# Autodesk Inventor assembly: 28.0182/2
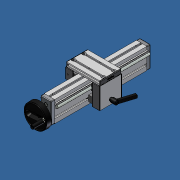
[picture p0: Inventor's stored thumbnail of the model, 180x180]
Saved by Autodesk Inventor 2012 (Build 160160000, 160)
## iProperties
Created: 2007-06
Part Number: 28.0182/2
Document SubType Name: Assembly
Designer: Andy Moles
Description: ADJUSTING UNIT VEW 45X90H WITH SIDE CLAMP
Author: Andy Moles
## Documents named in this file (24)
- C:\Andys Backup Data\ANDY'S INVENTOR\INVENTOR LIBRARIES\PARTS LIBRARY\READY FOR USE MODULES LG\28.0182_2 ADJUSTING UNIT VEW 45X90H WITH SIDE CLAMP.iam
- C:\Andys Backup Data\ANDY'S INVENTOR\INVENTOR LIBRARIES\PARTS LIBRARY\READY FOR USE MODULES LG\SUBCOMPONENTS\50.1264 BALL BEARING 10X30X9 6200 2RS DIN 625.ipt
- C:\Andys Backup Data\ANDY'S INVENTOR\INVENTOR LIBRARIES\PARTS LIBRARY\READY FOR USE MODULES LG\SUBCOMPONENTS\28.0200 BEARING PLATE 45X90 HANDWHEEL SIDE.ipt
- C:\Andys Backup Data\ANDY'S INVENTOR\INVENTOR LIBRARIES\PARTS LIBRARY\READY FOR USE MODULES LG\SUBCOMPONENTS\28.0201 BEARING PLATE 45X90 IDLER SIDE.ipt
- C:\Andys Backup Data\ANDY'S INVENTOR\INVENTOR LIBRARIES\PARTS LIBRARY\FASTENING ELEMENTS\SCREWS CAP\21.1204 M8X25.ipt
- C:\Andys Backup Data\ANDY'S INVENTOR\INVENTOR LIBRARIES\PARTS LIBRARY\FASTENING ELEMENTS\NUTS\21.1351 M8 SQUARE NUT.ipt
- C:\Andys Backup Data\ANDY'S INVENTOR\INVENTOR LIBRARIES\PARTS LIBRARY\READY FOR USE MODULES LG\SUBCOMPONENTS\28.0204 HANDWHEEL 100mm.iam
- C:\Andys Backup Data\ANDY'S INVENTOR\INVENTOR LIBRARIES\PARTS LIBRARY\READY FOR USE MODULES LG\SUBCOMPONENTS\28.0214 RAIL 45X90H.iam
- C:\Andys Backup Data\ANDY'S INVENTOR\INVENTOR LIBRARIES\PARTS LIBRARY\FASTENING ELEMENTS\WASHERS\21.1326 DISC SPRING 20.ipt
- C:\Andys Backup Data\ANDY'S INVENTOR\INVENTOR LIBRARIES\PARTS LIBRARY\READY FOR USE MODULES LG\SUBCOMPONENTS\28.0221 ACME SCREW 16X4.ipt
- C:\Andys Backup Data\ANDY'S INVENTOR\INVENTOR LIBRARIES\PARTS LIBRARY\READY FOR USE MODULES LG\SUBCOMPONENTS\28.0223_1 LWG 32X45-45 90X19-NSC.ipt
- C:\Andys Backup Data\ANDY'S INVENTOR\INVENTOR LIBRARIES\PARTS LIBRARY\READY FOR USE MODULES LG\SUBCOMPONENTS\28.0126 SLIDE 45X32.ipt
- C:\Andys Backup Data\ANDY'S INVENTOR\INVENTOR LIBRARIES\PARTS LIBRARY\FASTENING ELEMENTS\SCREWS CAP\21.1200 M8X16.ipt
- C:\Andys Backup Data\ANDY'S INVENTOR\INVENTOR LIBRARIES\PARTS LIBRARY\FASTENING ELEMENTS\SCREWS CAP\21.1235 M5X16.ipt
- C:\Andys Backup Data\ANDY'S INVENTOR\INVENTOR LIBRARIES\PARTS LIBRARY\END CAPS\22.1003_1 END CAP 45x32 Z Gray.iam
- C:\Andys Backup Data\ANDY'S INVENTOR\INVENTOR LIBRARIES\PARTS LIBRARY\READY FOR USE MODULES LG\SUBCOMPONENTS\28.9126 SIDE CLAMP 90X32.ipt
- C:\Andys Backup Data\ANDY'S INVENTOR\INVENTOR LIBRARIES\PARTS LIBRARY\COMPONENTS LG\22.1094 SLIDE RAIL LG.iam
- C:\Andys Backup Data\ANDY'S INVENTOR\INVENTOR LIBRARIES\PARTS LIBRARY\READY FOR USE MODULES LG\SUBCOMPONENTS\28.0256 Nut slide connector 38.5.ipt
- C:\Andys Backup Data\ANDY'S INVENTOR\INVENTOR LIBRARIES\PARTS LIBRARY\READY FOR USE MODULES LG\SUBCOMPONENTS\28.9127 SIDE LOCK SLIDE BAR 23.ipt
- C:\Andys Backup Data\ANDY'S INVENTOR\INVENTOR LIBRARIES\PARTS LIBRARY\COMPONENTS LG\21.1014_1 SLIDE LOCK WITH M6X65 STUD.ipt
- C:\Andys Backup Data\ANDY'S INVENTOR\INVENTOR LIBRARIES\PARTS LIBRARY\FASTENING ELEMENTS\NUTS\21.1330 M6 SQUARE NUT.ipt
- C:\Andys Backup Data\ANDY'S INVENTOR\INVENTOR LIBRARIES\PARTS LIBRARY\END CAPS\22.1014_1 END CAP 90X19 GRAY.ipt
- C:\Andys Backup Data\ANDY'S INVENTOR\INVENTOR LIBRARIES\PARTS LIBRARY\END CAPS\22.1061_1 END CAP 90X32 GRAY.ipt
- C:\Andys Backup Data\ANDY'S INVENTOR\INVENTOR LIBRARIES\PARTS LIBRARY\READY FOR USE MODULES LG\SUBCOMPONENTS\28.0257 BRONZE NUT 16X4 NOTCHED.ipt
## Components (39 placed, 23 different names)
1. 28.0214 RAIL 45X90H:1 [sub-assembly] — Mate:10, Flush:8, Flush:9, Flush:10, Flush:11, Flush:12, Mate:12, Flush:13, Flush:14, Angle:12, Angle:13, Mate:40
2. 50.1264 10X30X9 6200 2RS DIN 625 BALL BEARING:1 — Insert:11
3. 50.1264 10X30X9 6200 2RS DIN 625 BALL BEARING:2 — Insert:10, Insert:14
4. 28.0200 BEARING PLATE 45X90 HANDWHEEL SIDE:1 — Insert:4, Insert:5, Insert:9, Insert:11, Angle:2, Mate:12, Flush:13, Flush:14, Angle:14
5. 28.0201 BEARING PLATE 45X90 IDLER SIDE:1 — Insert:6, Insert:7, Insert:10, Angle:2, Mate:10, Flush:8, Flush:9
6. 21.1204  M8 x 25:1 — Insert:4
7. 21.1204  M8 x 25:2 — Insert:5
8. 21.1204  M8 x 25:3 — Insert:6
9. 21.1204  M8 x 25:4 — Insert:7
10. 28.0204 HANDWHEEL 100mm:1 [sub-assembly] — Insert:9
11. 21.1326 DISC SPRING 20:1 — Insert:12
12. 21.1326 DISC SPRING 20:2 — Insert:13, Insert:14
13. 28.0221 ACME SCREW 16X4:1 — Insert:12, Insert:13, Mate:39
14. 28.0223_1 LWG 32X45-45 90X19-NSC:1 — Mate:16, Flush:15, Flush:16, Insert:15, Insert:16, Insert:17, Insert:18, Insert:19, Insert:20, Mate:26, Flush:17, Flush:18, Flush:20, Angle:8, Insert:23, Angle:9, Mate:35, Flush:21, Mate:36, Flush:23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
15. 28.0126 SLIDE 45X32:1 — Mate:16, Flush:15, Flush:16, Mate:20, Mate:21, Angle:4, Angle:5, Mate:27, Insert:21, Insert:22, Angle:6, Angle:7, Mate:30, Mate:31
16. 21.1200 M8 x 16:1 — Insert:15, Mate:25
17. 21.1200 M8 x 16:2 — Insert:18, Mate:24
18. 21.1200 M8 x 16:3 — Insert:17, Mate:22
19. 21.1200 M8 x 16:4 — Insert:16, Mate:23
20. 21.1235  M5 x 16:1 — Insert:19
21. 21.1235  M5 x 16:2 — Insert:20
22. 21.1351 M8 SQUARE NUT:2 — Mate:24, Angle:4, Mate:27
23. 21.1351 M8 SQUARE NUT:3 — Mate:23, Mate:32, Angle:8
24. 21.1351 M8 SQUARE NUT:4 — Mate:20, Mate:25
25. 21.1351 M8 SQUARE NUT:5 — Mate:21, Mate:22, Angle:5
26. 22.1003\1 END CAP 45x32 Z Gray:1 [sub-assembly] — Insert:22, Angle:6
27. 22.1003\1 END CAP 45x32 Z Gray:2 [sub-assembly] — Insert:21, Angle:7
28. 28.9126 SIDE CLAMP 90X32:1 — Mate:26, Flush:17, Flush:18, Mate:28, Flush:19, Mate:29, Mate:32, Mate:33, Mate:34, Angle:10, Insert:24, Flush:22, Mate:37, Flush:25, Flush:26, Mate:38, Flush:27, Flush:28, Angle:12
29. 22.1094 SLIDE RAIL LG:1 [sub-assembly] — Mate:28, Flush:19, Mate:29
30. 22.1094 SLIDE RAIL LG:2 [sub-assembly] — Mate:30, Flush:20, Mate:31, Mate:40
31. 28.0256 Nut slide connector 38.5:1 — Insert:23, Angle:9, Mate:41
32. 28.9127 SIDE LOCK SLIDE BAR 23:1 — Mate:33, Mate:34, Angle:10, Angle:11, Mate:43
33. 21.1014_1 SLIDE LOCK WITH M6X65 STUD:1 — Insert:24, Mate:42
34. 21.1330 M6 SQUARE NUT:1 — Angle:11, Mate:42, Mate:43
35. 22.1014_1 END CAP 90X19 GRAY:1 — Mate:35, Flush:21, Flush:22
36. 22.1014_1 END CAP 90X19 GRAY:2 — Mate:36, Flush:23, Flush:24
37. 22.1061_1 END CAP 90X32 GRAY:1 — Mate:37, Flush:25, Flush:26
38. 22.1061_1 END CAP 90X32 GRAY:2 — Mate:38, Flush:27, Flush:28
39. 28.0257 BRONZE NUT 16X4 NOTCHED:1 — Mate:39, Angle:13, Angle:14, Mate:41
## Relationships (80: Mate 27, Flush 21, Insert 20, Angle 12)
- Insert:4: 28.0200 BEARING PLATE 45X90 HANDWHEEL SIDE:1 ↔ 21.1204  M8 x 25:1
- Insert:5: 28.0200 BEARING PLATE 45X90 HANDWHEEL SIDE:1 ↔ 21.1204  M8 x 25:2
- Insert:6: 28.0201 BEARING PLATE 45X90 IDLER SIDE:1 ↔ 21.1204  M8 x 25:3
- Insert:7: 28.0201 BEARING PLATE 45X90 IDLER SIDE:1 ↔ 21.1204  M8 x 25:4
- Insert:9: 28.0200 BEARING PLATE 45X90 HANDWHEEL SIDE:1 ↔ 28.0204 HANDWHEEL 100mm:1
- Insert:10: 50.1264 10X30X9 6200 2RS DIN 625 BALL BEARING:2 ↔ 28.0201 BEARING PLATE 45X90 IDLER SIDE:1
- Insert:11: 50.1264 10X30X9 6200 2RS DIN 625 BALL BEARING:1 ↔ 28.0200 BEARING PLATE 45X90 HANDWHEEL SIDE:1
- Angle:2: 28.0200 BEARING PLATE 45X90 HANDWHEEL SIDE:1 ↔ 28.0201 BEARING PLATE 45X90 IDLER SIDE:1
- Mate:10: 28.0214 RAIL 45X90H:1 ↔ 28.0201 BEARING PLATE 45X90 IDLER SIDE:1
- Flush:8: 28.0214 RAIL 45X90H:1 ↔ 28.0201 BEARING PLATE 45X90 IDLER SIDE:1
- Flush:9: 28.0214 RAIL 45X90H:1 ↔ 28.0201 BEARING PLATE 45X90 IDLER SIDE:1
- Flush:10: 28.0214 RAIL 45X90H:1
- Flush:11: 28.0214 RAIL 45X90H:1
- Flush:12: 28.0214 RAIL 45X90H:1
- Mate:12: 28.0214 RAIL 45X90H:1 ↔ 28.0200 BEARING PLATE 45X90 HANDWHEEL SIDE:1
- Flush:13: 28.0214 RAIL 45X90H:1 ↔ 28.0200 BEARING PLATE 45X90 HANDWHEEL SIDE:1
- Flush:14: 28.0214 RAIL 45X90H:1 ↔ 28.0200 BEARING PLATE 45X90 HANDWHEEL SIDE:1
- Insert:12: 21.1326 DISC SPRING 20:1 ↔ 28.0221 ACME SCREW 16X4:1
- Insert:13: 21.1326 DISC SPRING 20:2 ↔ 28.0221 ACME SCREW 16X4:1
- Insert:14: 50.1264 10X30X9 6200 2RS DIN 625 BALL BEARING:2 ↔ 21.1326 DISC SPRING 20:2
- Mate:16: 28.0223_1 LWG 32X45-45 90X19-NSC:1 ↔ 28.0126 SLIDE 45X32:1
- Flush:15: 28.0223_1 LWG 32X45-45 90X19-NSC:1 ↔ 28.0126 SLIDE 45X32:1
- Flush:16: 28.0223_1 LWG 32X45-45 90X19-NSC:1 ↔ 28.0126 SLIDE 45X32:1
- Insert:15: 28.0223_1 LWG 32X45-45 90X19-NSC:1 ↔ 21.1200 M8 x 16:1
- Insert:16: 28.0223_1 LWG 32X45-45 90X19-NSC:1 ↔ 21.1200 M8 x 16:4
- Insert:17: 28.0223_1 LWG 32X45-45 90X19-NSC:1 ↔ 21.1200 M8 x 16:3
- Insert:18: 28.0223_1 LWG 32X45-45 90X19-NSC:1 ↔ 21.1200 M8 x 16:2
- Insert:19: 28.0223_1 LWG 32X45-45 90X19-NSC:1 ↔ 21.1235  M5 x 16:1
- Insert:20: 28.0223_1 LWG 32X45-45 90X19-NSC:1 ↔ 21.1235  M5 x 16:2
- Mate:20: 28.0126 SLIDE 45X32:1 ↔ 21.1351 M8 SQUARE NUT:4
- Mate:21: 28.0126 SLIDE 45X32:1 ↔ 21.1351 M8 SQUARE NUT:5
- Mate:22: 21.1200 M8 x 16:3 ↔ 21.1351 M8 SQUARE NUT:5
- Mate:23: 21.1200 M8 x 16:4 ↔ 21.1351 M8 SQUARE NUT:3
- Mate:24: 21.1200 M8 x 16:2 ↔ 21.1351 M8 SQUARE NUT:2
- Mate:25: 21.1200 M8 x 16:1 ↔ 21.1351 M8 SQUARE NUT:4
- Angle:4: 28.0126 SLIDE 45X32:1 ↔ 21.1351 M8 SQUARE NUT:2
- Angle:5: 28.0126 SLIDE 45X32:1 ↔ 21.1351 M8 SQUARE NUT:5
- Mate:26: 28.0223_1 LWG 32X45-45 90X19-NSC:1 ↔ 28.9126 SIDE CLAMP 90X32:1
- Flush:17: 28.0223_1 LWG 32X45-45 90X19-NSC:1 ↔ 28.9126 SIDE CLAMP 90X32:1
- Flush:18: 28.0223_1 LWG 32X45-45 90X19-NSC:1 ↔ 28.9126 SIDE CLAMP 90X32:1
- Mate:27: 28.0126 SLIDE 45X32:1 ↔ 21.1351 M8 SQUARE NUT:2
- Insert:21: 28.0126 SLIDE 45X32:1 ↔ 22.1003\1 END CAP 45x32 Z Gray:2
- Insert:22: 28.0126 SLIDE 45X32:1 ↔ 22.1003\1 END CAP 45x32 Z Gray:1
- Angle:6: 28.0126 SLIDE 45X32:1 ↔ 22.1003\1 END CAP 45x32 Z Gray:1
- Angle:7: 28.0126 SLIDE 45X32:1 ↔ 22.1003\1 END CAP 45x32 Z Gray:2
- Mate:28: 28.9126 SIDE CLAMP 90X32:1 ↔ 22.1094 SLIDE RAIL LG:1
- Flush:19: 28.9126 SIDE CLAMP 90X32:1 ↔ 22.1094 SLIDE RAIL LG:1
- Mate:29: 28.9126 SIDE CLAMP 90X32:1 ↔ 22.1094 SLIDE RAIL LG:1
- Mate:30: 28.0126 SLIDE 45X32:1 ↔ 22.1094 SLIDE RAIL LG:2
- Flush:20: 28.0223_1 LWG 32X45-45 90X19-NSC:1 ↔ 22.1094 SLIDE RAIL LG:2
- Mate:31: 28.0126 SLIDE 45X32:1 ↔ 22.1094 SLIDE RAIL LG:2
- Mate:32: 21.1351 M8 SQUARE NUT:3 ↔ 28.9126 SIDE CLAMP 90X32:1
- Angle:8: 28.0223_1 LWG 32X45-45 90X19-NSC:1 ↔ 21.1351 M8 SQUARE NUT:3
- Insert:23: 28.0223_1 LWG 32X45-45 90X19-NSC:1 ↔ 28.0256 Nut slide connector 38.5:1
- Angle:9: 28.0223_1 LWG 32X45-45 90X19-NSC:1 ↔ 28.0256 Nut slide connector 38.5:1
- Mate:33: 28.9126 SIDE CLAMP 90X32:1 ↔ 28.9127 SIDE LOCK SLIDE BAR 23:1
- Mate:34: 28.9126 SIDE CLAMP 90X32:1 ↔ 28.9127 SIDE LOCK SLIDE BAR 23:1
- Angle:10: 28.9126 SIDE CLAMP 90X32:1 ↔ 28.9127 SIDE LOCK SLIDE BAR 23:1
- Insert:24: 28.9126 SIDE CLAMP 90X32:1 ↔ 21.1014_1 SLIDE LOCK WITH M6X65 STUD:1
- Angle:11: 28.9127 SIDE LOCK SLIDE BAR 23:1 ↔ 21.1330 M6 SQUARE NUT:1
- Mate:35: 28.0223_1 LWG 32X45-45 90X19-NSC:1 ↔ 22.1014_1 END CAP 90X19 GRAY:1
- Flush:21: 28.0223_1 LWG 32X45-45 90X19-NSC:1 ↔ 22.1014_1 END CAP 90X19 GRAY:1
- Flush:22: 28.9126 SIDE CLAMP 90X32:1 ↔ 22.1014_1 END CAP 90X19 GRAY:1
- Mate:36: 28.0223_1 LWG 32X45-45 90X19-NSC:1 ↔ 22.1014_1 END CAP 90X19 GRAY:2
- Flush:23: 28.0223_1 LWG 32X45-45 90X19-NSC:1 ↔ 22.1014_1 END CAP 90X19 GRAY:2
- Flush:24: 28.0223_1 LWG 32X45-45 90X19-NSC:1 ↔ 22.1014_1 END CAP 90X19 GRAY:2
- Mate:37: 28.9126 SIDE CLAMP 90X32:1 ↔ 22.1061_1 END CAP 90X32 GRAY:1
- Flush:25: 28.9126 SIDE CLAMP 90X32:1 ↔ 22.1061_1 END CAP 90X32 GRAY:1
- Flush:26: 28.9126 SIDE CLAMP 90X32:1 ↔ 22.1061_1 END CAP 90X32 GRAY:1
- Mate:38: 28.9126 SIDE CLAMP 90X32:1 ↔ 22.1061_1 END CAP 90X32 GRAY:2
- Flush:27: 28.9126 SIDE CLAMP 90X32:1 ↔ 22.1061_1 END CAP 90X32 GRAY:2
- Flush:28: 28.9126 SIDE CLAMP 90X32:1 ↔ 22.1061_1 END CAP 90X32 GRAY:2
- Angle:12: 28.0214 RAIL 45X90H:1 ↔ 28.9126 SIDE CLAMP 90X32:1
- Mate:39: 28.0221 ACME SCREW 16X4:1 ↔ 28.0257 BRONZE NUT 16X4 NOTCHED:1
- Angle:13: 28.0214 RAIL 45X90H:1 ↔ 28.0257 BRONZE NUT 16X4 NOTCHED:1
- Angle:14: 28.0200 BEARING PLATE 45X90 HANDWHEEL SIDE:1 ↔ 28.0257 BRONZE NUT 16X4 NOTCHED:1
- Mate:40: 28.0214 RAIL 45X90H:1 ↔ 22.1094 SLIDE RAIL LG:2
- Mate:41: 28.0256 Nut slide connector 38.5:1 ↔ 28.0257 BRONZE NUT 16X4 NOTCHED:1
- Mate:42: 21.1014_1 SLIDE LOCK WITH M6X65 STUD:1 ↔ 21.1330 M6 SQUARE NUT:1
- Mate:43: 28.9127 SIDE LOCK SLIDE BAR 23:1 ↔ 21.1330 M6 SQUARE NUT:1
